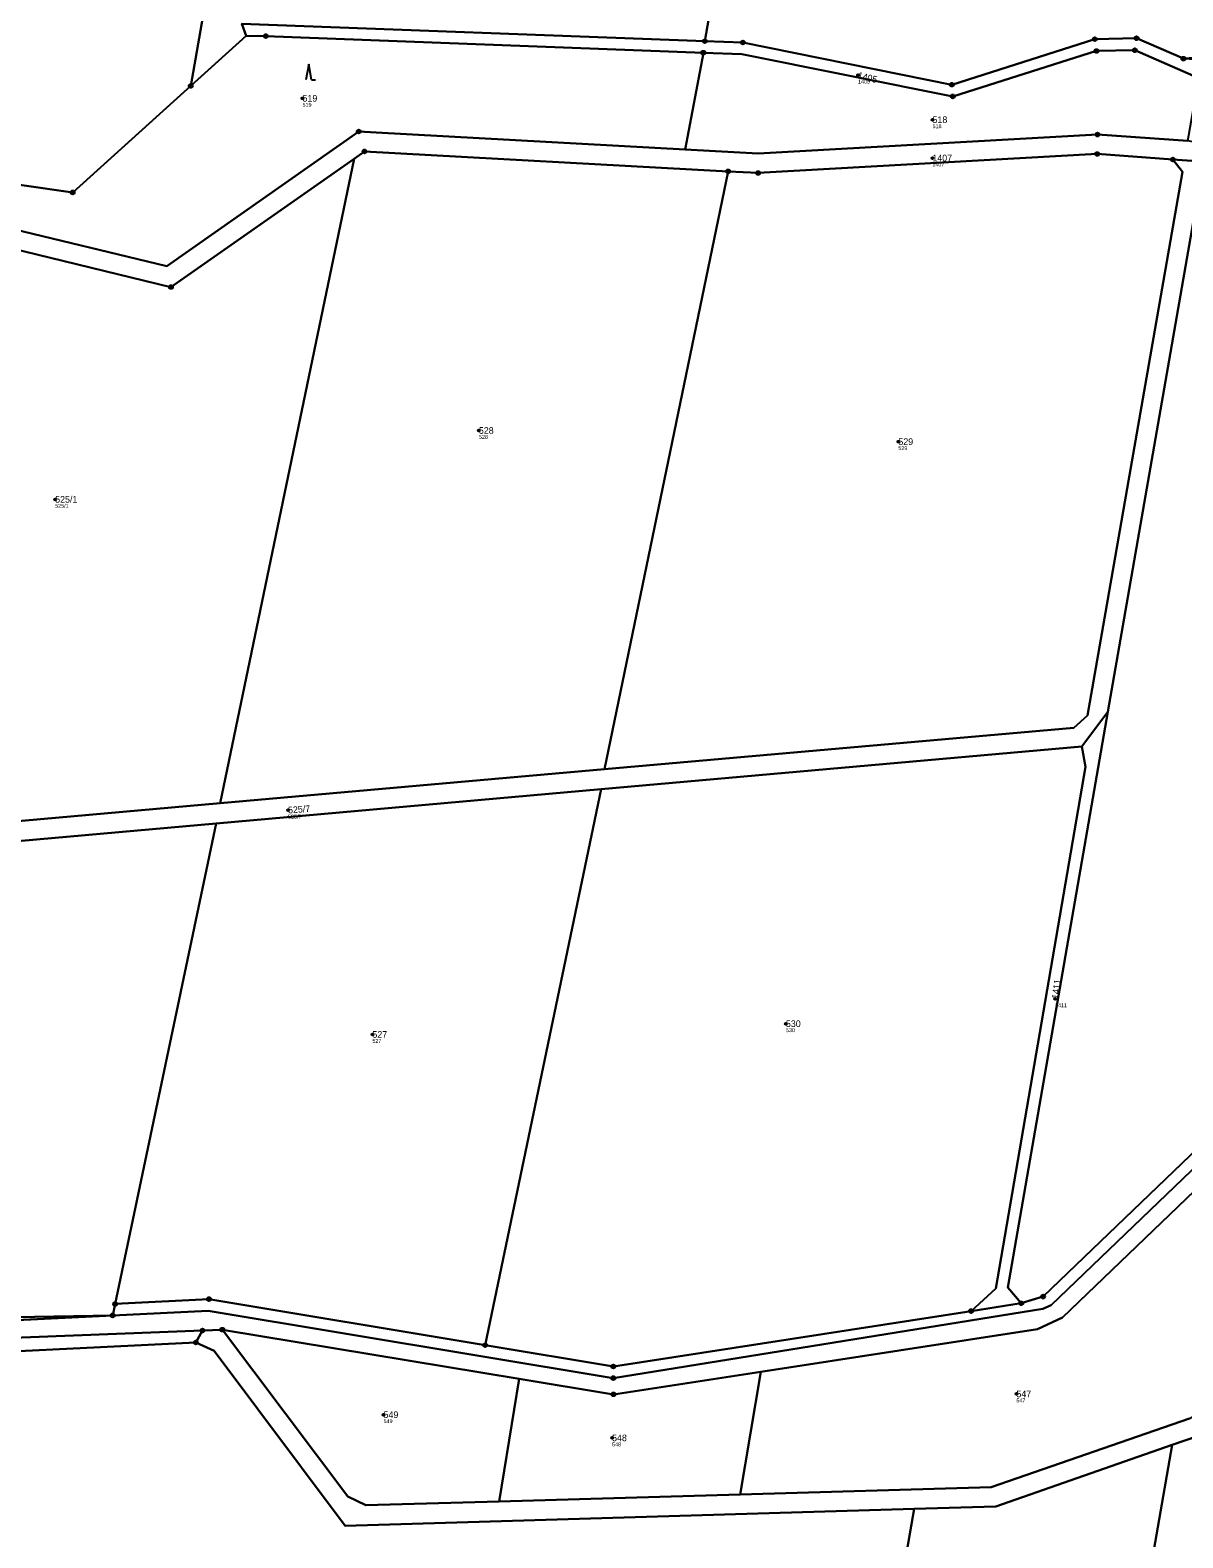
# Model space of a CAD drawing. Extents: x -658203 to -653176, y -1156738 to -1151709.
# Drawn here: x -656083.2 to -655787.1, y -1154775.1 to -1154387.9 of the extents above; entities that cross this region are included whole.
import ezdxf

# ---------------------------------------------------------------- set-up
doc = ezdxf.new("R2010")
doc.units = 0
for name, color, linetype in [('Vrstva 1', 7, 'Continuous'), ('Vrstva 2', 7, 'Continuous'), ('Vrstva 3', 7, 'Continuous'), ('Vrstva 50', 7, 'Continuous'), ('Vrstva 51', 7, 'Continuous'), ('Vrstva 8', 7, 'Continuous')]:
    doc.layers.add(name, color=color, linetype=linetype)

msp = doc.modelspace()

# ---------------------------------------------------------------- linework, layer by layer
at = {"layer": 'Vrstva 1'}
for p, q in [((-656041.97, -1154402.19), (-655997.96, -1154150.36)), ((-655877.54, -1154204.34), (-655909.91, -1154390.7)), ((-656027.78, -1154389.31), (-656041.97, -1154402.19)), ((-655910.29, -1154393.67), (-655914.99, -1154418.51)), ((-656034.45, -1154586.4), (-656000.02, -1154420.92)), ((-655789.66, -1154421.09), (-655778.7, -1154421.89)), ((-655935.7, -1154577.67), (-655903.93, -1154424.14)), ((-655806.39, -1154562.95), (-655813.02, -1154571.84)), ((-655813.02, -1154571.84), (-655936.51, -1154582.8)), ((-655935.7, -1154577.67), (-656034.45, -1154586.4)), ((-656035.41, -1154591.58), (-655936.51, -1154582.8)), ((-655936.51, -1154582.8), (-655966.35, -1154725.57)), ((-656061.4, -1154715), (-656035.41, -1154591.58)), ((-656061.4, -1154715), (-656062.03, -1154717.93)), ((-655841.51, -1154716.82), (-655828.62, -1154714.82)), ((-656173.7, -1154723.39), (-656062.03, -1154717.93)), ((-656172.96, -1154719.81), (-656062.03, -1154717.93)), ((-656033.86, -1154721.6), (-656038.94, -1154721.8)), ((-655957.63, -1154734.2), (-656033.86, -1154721.6)), ((-656122.96, -1154728.88), (-656040.69, -1154724.88)), ((-656040.69, -1154724.88), (-656038.94, -1154721.8)), ((-655895.55, -1154732.4), (-655900.83, -1154763.93)), ((-655957.63, -1154734.2), (-655962.71, -1154765.71)), ((-655805.94, -1154843.65), (-655789.83, -1154751.19)), ((-655962.71, -1154765.71), (-655900.83, -1154763.93)), ((-655870.85, -1154852.58), (-655856.1, -1154767.64))]:
    msp.add_line(p, q, dxfattribs=at)
for points in [[(-655828.62, -1154714.82), (-655822.98, -1154713.09), (-655583.89, -1154483.81), (-655486.68, -1154462.26), (-655480.98, -1154456.45), (-655455.19, -1154309.3), (-655459.04, -1154305.85)], [(-655909.91, -1154390.7), (-656028.85, -1154386.28), (-656027.78, -1154389.31)], [(-655910.29, -1154393.67), (-656022.68, -1154389.4), (-656027.78, -1154389.31)], [(-655909.91, -1154390.7), (-655900.12, -1154391.06), (-655846.46, -1154401.89), (-655809.71, -1154390.2), (-655798.99, -1154389.96), (-655786.95, -1154395.2)], [(-655783.01, -1154400.21), (-655799.45, -1154393.04), (-655809.27, -1154393.23), (-655846.22, -1154404.9), (-655900.4, -1154394.05), (-655910.29, -1154393.67)], [(-656111.64, -1154423.92), (-656072.31, -1154429.55), (-656041.97, -1154402.19)], [(-656111.73, -1154425.93), (-656089.98, -1154438.41), (-656048.14, -1154448.46), (-655998.81, -1154413.91), (-655994.32, -1154414.18), (-655914.99, -1154418.51)], [(-655914.99, -1154418.51), (-655896.22, -1154419.53), (-655809.03, -1154414.69), (-655785.84, -1154416.31)], [(-656000.02, -1154420.92), (-655997.33, -1154419.03), (-655903.93, -1154424.14)], [(-655903.93, -1154424.14), (-655896.23, -1154424.56), (-655809.09, -1154419.67), (-655789.66, -1154421.09)], [(-656000.02, -1154420.92), (-656047.06, -1154453.85), (-656091.81, -1154443.05), (-656113.17, -1154430.82)], [(-655789.66, -1154421.09), (-655787.21, -1154424.25), (-655811.62, -1154563.86), (-655815.12, -1154567.01), (-655935.7, -1154577.67)], [(-655778.7, -1154421.89), (-655782.18, -1154424.52), (-655806.39, -1154562.95)], [(-656062.03, -1154717.93), (-656037.49, -1154716.73), (-655933.42, -1154734.02), (-655823.08, -1154716.25), (-655820.9, -1154715.26), (-655581.81, -1154485.98), (-655479.22, -1154463.77)], [(-655806.39, -1154562.95), (-655832.04, -1154710.78), (-655828.62, -1154714.82)], [(-655841.51, -1154716.82), (-655835.16, -1154711.01), (-655812.09, -1154577.06), (-655813.02, -1154571.84)], [(-656147.26, -1154596.38), (-656093.15, -1154591.59), (-656034.45, -1154586.4)], [(-656035.41, -1154591.58), (-656094.17, -1154596.79), (-656148.43, -1154601.56)], [(-655789.83, -1154751.19), (-655783.32, -1154748.92), (-655709.46, -1154707.55), (-655650.95, -1154615.45), (-655645.63, -1154610.18)], [(-655767.19, -1154669.68), (-655817.98, -1154718.44), (-655824.46, -1154721.48), (-655895.55, -1154732.4)], [(-656038.94, -1154721.8), (-656229.04, -1154729.18), (-656325.62, -1154709.67), (-656339.85, -1154708.24), (-656345.78, -1154710.5)], [(-655966.35, -1154725.57), (-656037.3, -1154713.74), (-656061.4, -1154715)], [(-655966.35, -1154725.57), (-655933.41, -1154731.06), (-655841.51, -1154716.82)], [(-656033.86, -1154721.6), (-656001.66, -1154764.45), (-655996.99, -1154766.7), (-655962.71, -1154765.71)], [(-655856.1, -1154767.64), (-656002.29, -1154771.94), (-656035.93, -1154727.06), (-656040.69, -1154724.88)], [(-655895.55, -1154732.4), (-655933.39, -1154738.21), (-655957.63, -1154734.2)], [(-655900.83, -1154763.93), (-655836.36, -1154762.08), (-655785.37, -1154744.38), (-655779.45, -1154741.05)], [(-655789.83, -1154751.19), (-655835.13, -1154767.02), (-655856.1, -1154767.64)]]:
    msp.add_lwpolyline(points, dxfattribs=at)
at = {"layer": 'Vrstva 3'}
for p, q in [((-656011.67, -1154396.61), (-656012.42, -1154400.61)), ((-656010.92, -1154400.61), (-656011.67, -1154396.61)), ((-656010.92, -1154400.61), (-656009.92, -1154400.61))]:
    msp.add_line(p, q, dxfattribs=at)
at = {"layer": 'Vrstva 50'}
for centre in [(-655870.55, -1154399.42), (-656013.26, -1154405.39), (-655851.4, -1154410.89), (-655851.44, -1154420.72), (-655967.95, -1154490.68), (-655860.18, -1154493.56), (-656076.81, -1154508.38), (-656016.98, -1154588.18), (-655819.92, -1154636.63), (-655889.07, -1154643.03), (-655995.31, -1154645.78), (-655829.85, -1154738.09), (-655992.44, -1154743.43), (-655933.73, -1154749.39)]:
    msp.add_circle(centre, 0.25, dxfattribs=at)
at = {"layer": 'Vrstva 51'}
for points in [[(-656111.64, -1154423.92), (-656072.31, -1154429.55), (-656041.97, -1154402.19), (-655997.96, -1154150.36), (-656041.06, -1154128.73), (-656185.4, -1154090.22), (-656241.8, -1154416.36)], [(-655909.91, -1154390.7), (-655877.54, -1154204.34), (-655917.6, -1154190.78), (-655997.96, -1154150.36), (-656041.97, -1154402.19), (-656027.78, -1154389.31), (-656028.85, -1154386.28)], [(-655809.71, -1154390.2), (-655798.99, -1154389.96), (-655786.95, -1154395.2), (-655781.81, -1154394.53), (-655756.63, -1154249.72), (-655758.48, -1154244.65), (-655877.54, -1154204.34), (-655909.91, -1154390.7), (-655900.12, -1154391.06), (-655846.46, -1154401.89)], [(-655451.73, -1154308.38), (-655448.2, -1154302.34), (-655459.04, -1154305.85), (-655455.19, -1154309.3), (-655480.98, -1154456.45), (-655486.68, -1154462.26), (-655583.89, -1154483.81), (-655822.98, -1154713.09), (-655828.62, -1154714.82), (-655841.51, -1154716.82), (-655933.41, -1154731.06), (-655966.35, -1154725.57), (-656037.3, -1154713.74), (-656061.4, -1154715), (-656062.03, -1154717.93), (-656037.49, -1154716.73), (-655933.42, -1154734.02), (-655823.08, -1154716.25), (-655820.9, -1154715.26), (-655581.81, -1154485.98), (-655479.22, -1154463.77)], [(-655480.98, -1154456.45), (-655455.19, -1154309.3), (-655459.04, -1154305.85), (-655573.64, -1154343.18), (-655686.08, -1154403), (-655724.05, -1154420.02), (-655733.45, -1154423.25), (-655745.34, -1154424.24), (-655778.7, -1154421.89), (-655782.18, -1154424.52), (-655806.39, -1154562.95), (-655832.04, -1154710.78), (-655828.62, -1154714.82), (-655822.98, -1154713.09), (-655583.89, -1154483.81), (-655486.68, -1154462.26)], [(-656048.14, -1154448.46), (-655998.81, -1154413.91), (-655994.32, -1154414.18), (-655914.99, -1154418.51), (-655910.29, -1154393.67), (-656022.68, -1154389.4), (-656027.78, -1154389.31), (-656041.97, -1154402.19), (-656072.31, -1154429.55), (-656111.64, -1154423.92), (-656111.73, -1154425.93), (-656089.98, -1154438.41)], [(-655785.84, -1154416.31), (-655783.01, -1154400.21), (-655799.45, -1154393.04), (-655809.27, -1154393.23), (-655846.22, -1154404.9), (-655900.4, -1154394.05), (-655910.29, -1154393.67), (-655914.99, -1154418.51), (-655896.22, -1154419.53), (-655809.03, -1154414.69)], [(-655935.7, -1154577.67), (-655903.93, -1154424.14), (-655997.33, -1154419.03), (-656000.02, -1154420.92), (-656034.45, -1154586.4)], [(-655789.66, -1154421.09), (-655809.09, -1154419.67), (-655896.23, -1154424.56), (-655903.93, -1154424.14), (-655935.7, -1154577.67), (-655815.12, -1154567.01), (-655811.62, -1154563.86), (-655787.21, -1154424.25)], [(-655789.66, -1154421.09), (-655787.21, -1154424.25), (-655811.62, -1154563.86), (-655815.12, -1154567.01), (-655935.7, -1154577.67), (-656034.45, -1154586.4), (-656093.15, -1154591.59), (-656147.26, -1154596.38), (-656266.84, -1154606.95), (-656320.16, -1154611.66), (-656356.88, -1154614.91), (-656357.91, -1154619.96), (-656335, -1154617.98), (-656333.9, -1154617.88), (-656267.8, -1154612.07), (-656148.43, -1154601.56), (-656094.17, -1154596.79), (-656035.41, -1154591.58), (-655936.51, -1154582.8), (-655813.02, -1154571.84), (-655806.39, -1154562.95), (-655782.18, -1154424.52), (-655778.7, -1154421.89)], [(-656091.81, -1154443.05), (-656113.17, -1154430.82), (-656147.26, -1154596.38), (-656093.15, -1154591.59), (-656034.45, -1154586.4), (-656000.02, -1154420.92), (-656047.06, -1154453.85)], [(-655813.02, -1154571.84), (-655812.09, -1154577.06), (-655835.16, -1154711.01), (-655841.51, -1154716.82), (-655828.62, -1154714.82), (-655832.04, -1154710.78), (-655806.39, -1154562.95)], [(-655936.51, -1154582.8), (-655966.35, -1154725.57), (-655933.41, -1154731.06), (-655841.51, -1154716.82), (-655835.16, -1154711.01), (-655812.09, -1154577.06), (-655813.02, -1154571.84)], [(-655966.35, -1154725.57), (-655936.51, -1154582.8), (-656035.41, -1154591.58), (-656061.4, -1154715), (-656037.3, -1154713.74)], [(-656035.41, -1154591.58), (-656094.17, -1154596.79), (-656148.43, -1154601.56), (-656172.96, -1154719.81), (-656062.03, -1154717.93), (-656061.4, -1154715)], [(-655683.1, -1154826.74), (-655645.63, -1154610.18), (-655650.95, -1154615.45), (-655709.46, -1154707.55), (-655783.32, -1154748.92), (-655789.83, -1154751.19), (-655805.94, -1154843.65), (-655798.51, -1154842.63)], [(-655824.46, -1154721.48), (-655895.55, -1154732.4), (-655900.83, -1154763.93), (-655836.36, -1154762.08), (-655785.37, -1154744.38), (-655779.45, -1154741.05), (-655767.19, -1154669.68), (-655817.98, -1154718.44)], [(-656038.94, -1154721.8), (-656229.04, -1154729.18), (-656325.62, -1154709.67), (-656339.85, -1154708.24), (-656345.78, -1154710.5), (-656303.74, -1154719.05), (-656284.44, -1154722.98), (-656239.62, -1154732.1), (-656229.45, -1154734.06), (-656215.86, -1154733.4), (-656168.81, -1154731.11), (-656122.96, -1154728.88), (-656040.69, -1154724.88)], [(-656173.7, -1154723.39), (-656062.03, -1154717.93), (-656172.96, -1154719.81)], [(-655996.99, -1154766.7), (-655962.71, -1154765.71), (-655957.63, -1154734.2), (-656033.86, -1154721.6), (-656001.66, -1154764.45)], [(-655870.85, -1154852.58), (-655856.1, -1154767.64), (-656002.29, -1154771.94), (-656035.93, -1154727.06), (-656040.69, -1154724.88), (-656122.96, -1154728.88), (-656150.75, -1154891.12), (-656017.7, -1154872.77)], [(-655962.71, -1154765.71), (-655900.83, -1154763.93), (-655895.55, -1154732.4), (-655933.39, -1154738.21), (-655957.63, -1154734.2)], [(-655856.1, -1154767.64), (-655870.85, -1154852.58), (-655805.94, -1154843.65), (-655789.83, -1154751.19), (-655835.13, -1154767.02)]]:
    msp.add_lwpolyline(points, close=True, dxfattribs=at)
for points in [[(-656091.81, -1154443.05), (-656047.06, -1154453.85), (-656000.02, -1154420.92), (-655997.33, -1154419.03), (-655903.93, -1154424.14), (-655896.23, -1154424.56), (-655809.09, -1154419.67), (-655789.66, -1154421.09), (-655778.7, -1154421.89), (-655745.34, -1154424.24), (-655733.45, -1154423.25), (-655724.05, -1154420.02), (-655686.08, -1154403), (-655573.64, -1154343.18)], [(-655696.55, -1154374.3), (-655753.4, -1154396.07), (-655772.34, -1154396.79), (-655786.95, -1154395.2), (-655798.99, -1154389.96), (-655809.71, -1154390.2), (-655846.46, -1154401.89), (-655900.12, -1154391.06), (-655909.91, -1154390.7), (-656028.85, -1154386.28), (-656027.78, -1154389.31), (-656022.68, -1154389.4), (-655910.29, -1154393.67), (-655900.4, -1154394.05), (-655846.22, -1154404.9), (-655809.27, -1154393.23), (-655799.45, -1154393.04), (-655783.01, -1154400.21), (-655777.82, -1154400.59), (-655752.75, -1154399.59), (-655695.71, -1154377.4)], [(-655651.83, -1154379.18), (-655688.13, -1154398.75), (-655725.86, -1154415.73), (-655734.19, -1154418.72), (-655745.17, -1154419.73), (-655780.84, -1154417.31), (-655785.84, -1154416.31), (-655809.03, -1154414.69), (-655896.22, -1154419.53), (-655914.99, -1154418.51), (-655994.32, -1154414.18), (-655998.81, -1154413.91), (-656048.14, -1154448.46), (-656089.98, -1154438.41)], [(-655581.81, -1154485.98), (-655820.9, -1154715.26), (-655823.08, -1154716.25), (-655933.42, -1154734.02), (-656037.49, -1154716.73), (-656062.03, -1154717.93), (-656173.7, -1154723.39)], [(-656229.04, -1154729.18), (-656038.94, -1154721.8), (-656033.86, -1154721.6), (-655957.63, -1154734.2), (-655933.39, -1154738.21), (-655895.55, -1154732.4), (-655824.46, -1154721.48), (-655817.98, -1154718.44), (-655767.19, -1154669.68), (-655755.23, -1154658.2), (-655694.89, -1154600.27), (-655674.99, -1154581.17), (-655603.05, -1154512.1)], [(-655785.37, -1154744.38), (-655836.36, -1154762.08), (-655900.83, -1154763.93), (-655962.71, -1154765.71), (-655996.99, -1154766.7), (-656001.66, -1154764.45), (-656033.86, -1154721.6), (-656038.94, -1154721.8), (-656040.69, -1154724.88), (-656035.93, -1154727.06), (-656002.29, -1154771.94), (-655856.1, -1154767.64), (-655835.13, -1154767.02), (-655789.83, -1154751.19), (-655783.32, -1154748.92)]]:
    msp.add_lwpolyline(points, dxfattribs=at)
at = {"layer": 'Vrstva 8'}
for centre, radius in [((-656022.68, -1154389.4), 0.5), ((-656022.68, -1154389.4), 0.0303), ((-655909.91, -1154390.7), 0.5), ((-655909.91, -1154390.7), 0.0303), ((-655900.12, -1154391.06), 0.5), ((-655900.12, -1154391.06), 0.0303), ((-655809.71, -1154390.2), 0.5), ((-655809.71, -1154390.2), 0.0303), ((-655799.45, -1154393.04), 0.5), ((-655798.99, -1154389.96), 0.5), ((-655798.99, -1154389.96), 0.0303), ((-655910.29, -1154393.67), 0.5), ((-655910.29, -1154393.67), 0.0303), ((-655809.27, -1154393.23), 0.5), ((-655809.27, -1154393.23), 0.0303), ((-655799.45, -1154393.04), 0.0303), ((-655786.95, -1154395.2), 0.5), ((-656041.97, -1154402.19), 0.5), ((-656041.97, -1154402.19), 0.0303), ((-655846.46, -1154401.89), 0.5), ((-655846.46, -1154401.89), 0.0303), ((-655846.22, -1154404.9), 0.5), ((-655846.22, -1154404.9), 0.0303), ((-655998.81, -1154413.91), 0.5), ((-655998.81, -1154413.91), 0.0303), ((-655809.03, -1154414.69), 0.5), ((-655809.03, -1154414.69), 0.0303), ((-655997.33, -1154419.03), 0.5), ((-655997.33, -1154419.03), 0.0303), ((-655809.09, -1154419.67), 0.5), ((-655809.09, -1154419.67), 0.0303), ((-655903.93, -1154424.14), 0.5), ((-655789.66, -1154421.09), 0.5), ((-655789.66, -1154421.09), 0.0303), ((-655903.93, -1154424.14), 0.0303), ((-655896.23, -1154424.56), 0.5), ((-655896.23, -1154424.56), 0.0303), ((-656072.31, -1154429.55), 0.5), ((-656072.31, -1154429.55), 0.0303), ((-656047.06, -1154453.85), 0.5), ((-656047.06, -1154453.85), 0.0303), ((-656037.3, -1154713.74), 0.5), ((-656037.3, -1154713.74), 0.0303), ((-655822.98, -1154713.09), 0.5), ((-655822.98, -1154713.09), 0.0303), ((-656062.03, -1154717.93), 0.5), ((-656062.03, -1154717.93), 0.0303), ((-656061.4, -1154715), 0.5), ((-656061.4, -1154715), 0.0303), ((-655841.51, -1154716.82), 0.5), ((-655841.51, -1154716.82), 0.0303), ((-655828.62, -1154714.82), 0.5), ((-655828.62, -1154714.82), 0.0303), ((-656038.94, -1154721.8), 0.5), ((-656038.94, -1154721.8), 0.0303), ((-656033.86, -1154721.6), 0.5), ((-656033.86, -1154721.6), 0.0303), ((-656040.69, -1154724.88), 0.5), ((-656040.69, -1154724.88), 0.0303), ((-655966.35, -1154725.57), 0.5), ((-655966.35, -1154725.57), 0.0303), ((-655933.41, -1154731.06), 0.5), ((-655933.41, -1154731.06), 0.0303), ((-655933.42, -1154734.02), 0.5), ((-655933.42, -1154734.02), 0.0303), ((-655933.39, -1154738.21), 0.5), ((-655933.39, -1154738.21), 0.0303)]:
    msp.add_circle(centre, radius, dxfattribs=at)

# ---------------------------------------------------------------- texts
at = {"layer": 'Vrstva 2'}
for s, rotation, p in [('1405', 346, (-655870.76, -1154400.24)), ('525/7', 4, (-656016.92, -1154589.03)), ('1411', 83, (-655819.08, -1154636.73))]:
    msp.add_text(s, height=1.7, rotation=rotation, dxfattribs=at).set_placement(p)
for s, p in [('519', (-656013.26, -1154406.24)), ('518', (-655851.4, -1154411.74)), ('1407', (-655851.44, -1154421.57)), ('528', (-655967.95, -1154491.53)), ('529', (-655860.18, -1154494.41)), ('525/1', (-656076.81, -1154509.23)), ('530', (-655889.07, -1154643.88)), ('527', (-655995.31, -1154646.63)), ('547', (-655829.85, -1154738.94)), ('549', (-655992.44, -1154744.28)), ('548', (-655933.73, -1154750.24))]:
    msp.add_text(s, height=1.7, dxfattribs=at).set_placement(p)
at = {"layer": 'Vrstva 50'}
for s, p in [('1405', (-655870.55, -1154401.58)), ('519', (-656013.26, -1154407.55)), ('518', (-655851.4, -1154413.05)), ('1407', (-655851.44, -1154422.88)), ('528', (-655967.95, -1154492.84)), ('529', (-655860.18, -1154495.72)), ('525/1', (-656076.81, -1154510.54)), ('525/7', (-656016.98, -1154590.34)), ('1411', (-655819.92, -1154638.79)), ('530', (-655889.07, -1154645.19)), ('527', (-655995.31, -1154647.94)), ('547', (-655829.85, -1154740.25)), ('549', (-655992.44, -1154745.59)), ('548', (-655933.73, -1154751.55))]:
    msp.add_text(s, height=1, dxfattribs=at).set_placement(p)

doc.saveas('drawing.dxf')
